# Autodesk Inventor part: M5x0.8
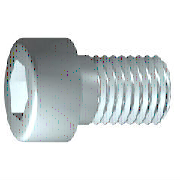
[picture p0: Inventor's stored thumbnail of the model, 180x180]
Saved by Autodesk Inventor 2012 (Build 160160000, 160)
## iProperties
IsCustomPart: 0
Manager: KYOUNG IL JANG
Company: 한국ATC센터
Created: 2009-02
Part Number: M5x0.8
Material: Steel, Mild
Description: 6각머리 태핑 나사
Document SubType Name: Modeling
Standard: KS B 1003
Standards Organization: KS
Language: ko-KR
Size Designation: M 5 x 20
Categories: <MemberInstance><Categories><Category DisplayName="조임쇠" InternalName="e4da775c-781d-43d5-af7c-5136215cf5a6" Mnemonic="FSTN"><Category DisplayName="볼트" InternalN
Density: 1 g/cm^3
Checked By: KYOUNG IL JANG
Vendor: CBT Solutions
Designer: KYOUNG IL JANG
Author: KYOUNG IL JANG
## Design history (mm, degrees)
workplane "Work Plane1"
fillet "Fillet2" dims "d30" = 0.1 (= R)
revolve "본체" stored, may be unused: angle "d10" = 90 deg
sketch "스케치2"
  geometry: L1 (0, -5.95)-(0, 5.95) reference; L2 (-5.95, 0)-(5.95, 0) reference; L3 (2.309, 0)-(1.155, -2); L4 (1.155, -2)-(-1.155, -2); L5 (-1.155, -2)-(-2.309, 0); L6 (-2.309, 0)-(-1.155, 2); L7 (-1.155, 2)-(1.155, 2); L8 (1.155, 2)-(2.309, 0); 2 further points
  constraints: 12 end point, 1 coincident, 1 horizontal alignment, 1 point on line, 12 other
extrude "슬롯" join sketch "스케치2" stored distance "d11" = 10; taper "d12" = 0 deg
body "Solid1"
fillet "모깎기1" dims "d17" = 0.5 (= RR)
feature "스레드" dims "d13" = 18 (= GEL), "d14" = 0
chamfer "모따기1" distance "d15" = 0.49076 (= -0.5 x SPD + 0.5 x GD); stored, may be unused: second distance "d16" = 0.49076 (= GUL), angle "d27" = 45 deg
sketch "스케치1"
  geometry: L1 (-1.167, 0)-(20, 0); L2 (20, 0)-(20, 2.5); L3 (20, 2.5)-(2, 2.5); L4 (2, 2.5)-(1.509, 2.5); L5 (1.509, 2.5)-(0, 2.5); L6 (0, 2.5)-(0, 4.25); L7 (0, 4.25)-(-5, 4.25); L8 (-5, 4.25)-(-5, 2.309); L9 (-5, 2.309)-(-2.5, 2.309); L10 (-2.5, 2.309)-(-1.167, 0); L11 (-10, 0)-(25, 0) reference; L12 (0, -0.85)-(0, 5.1) reference; L13 (2, 2.5)-(0, 2.5)
  constraints: 22 end point, 6 parallel, 2 collinear, 2 perpendicular, 1 horizontal, 1 point on line
  dimensions: "d1" = 18 distance from line of L3.end L2 (= GEL); "d2" = 0.49086 distance of L4.end L3.end (computed from GAL); "d3" = 5 distance between parallel lines of L8 L6 (= KOH); "d4" = 2.5 distance of L8.end L9.end (= INTI); "d5" = 60 deg angle of L10 L1; "d6" = 5 diameter of L3 L1 (= GD); "d7" = 5 diameter of L5 L1 (= BDM); "d8" = 4.6188 diameter of L9 L1 (= 1.1547 x SW); "d9" = 8.5 diameter of L7 L1 (= KOD); "d26" = 20 distance between parallel lines of L12 L2 (= NLG)
other parameters: "GD" = 5 (= NND) [user parameter; used in 2 equation terms], "NLG" = 20 [user parameter; used in 1 equation term], "GEL" = 18 [user parameter; used in 2 equation terms], "KOD" = 8.5 [user parameter; used in 1 equation term], "KOH" = 5 [user parameter; used in 1 equation term], "INTI" = 2.5 [user parameter; used in 1 equation term], "GAL" = 0.49076 (= 0.61345 x PTC) [user parameter; used in 1 equation term], "GUL" = 0.49076 (= 0.61345 x PTC) [user parameter; used in 1 equation term], "BDM" = 5 (= NND) [user parameter; used in 1 equation term], "SW" = 4 [user parameter; used in 2 equation terms], "RR" = 0.5 [user parameter; used in 1 equation term], "SPD" = 4.01848 (= NND - 1.2269 x PTC) [user parameter; used in 1 equation term], "d19" = 0, "d28" = 0, "d29" = 0, "R" = 0.1 [user parameter; used in 1 equation term], "PHH" = 0.2 [user parameter], "GD1" = 4.01848 (= THREADDIA - 1.2269 x PTC) [user parameter], "THREADDIA" = 5 [user parameter; used in 1 equation term], "FAWI" = 45 deg [user parameter], "TPU" = 12.5 (computed from PTC) [user parameter], "PTC" = 0.8 [user parameter; used in 5 equation terms], "NND" = 5 [user parameter; used in 3 equation terms], "TOA" = 30 deg [user parameter], "E0" = 4.62 (= 1.155 x SW) [user parameter]
